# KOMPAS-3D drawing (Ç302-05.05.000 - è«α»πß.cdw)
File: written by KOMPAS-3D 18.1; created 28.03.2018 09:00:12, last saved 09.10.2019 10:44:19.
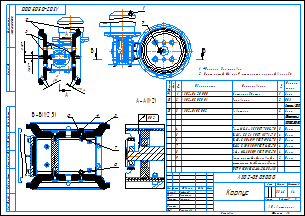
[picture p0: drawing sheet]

Sheet 1: A3, landscape

Document properties: Автор: Милов; Полное имя файла: ..\3Д ПВХ\А302-01.05.000 - Корпус.a3d; Масса: 33.4594

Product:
- Part/product: (unnamed)
  - Component: Болт М8-6gx35 ГОСТ 7805-70  | pos. 4  | Раздел спецификации: Стандартные изделия; Примечание: Нерж.
  - Component: Ловитель  | designation А302-01.05.002  | pos. 3  | Раздел спецификации: Детали; Форматы листов документа: А3; Примечание: Заим. / Фторопласт-4  / ГОСТ 10007-80 Е @2~50
  - Component: Основание  | designation А302-05.05.001  | pos. 2  | Раздел спецификации: Детали; Форматы листов документа: А3; Примечание: ПВХ / Стержень @2~300
  - Component: Мотор-редуктор  | designation А302-04.20.000  | pos. 1  | Раздел спецификации: Сборочные единицы; Форматы листов документа: *); Примечание: Заим.
  - Component: Шайба C.8.21 ГОСТ 11371-78  | pos. 5  | Раздел спецификации: Стандартные изделия; Примечание: Нерж.
  - Component: Шайба C 8.04.019 ГОСТ 6958-78  | pos. 6  | Раздел спецификации: Стандартные изделия; Примечание: Нерж.
  - Component: Шайба 8 30Х13 019 ГОСТ 6402-70  | pos. 7  | Раздел спецификации: Стандартные изделия; Примечание: Нерж.
  - Component: Гайка М8-6H.5.019 ГОСТ 5915-70  | pos. 8  | Раздел спецификации: Стандартные изделия; Примечание: Нерж
  - Component: Винт с потайной головкой и  / шестигранным углублением под ключ / ГОСТ Р ИСО 10642-М4x20-8.8-A3J  | pos. 9  | Раздел спецификации: Стандартные изделия; Примечание: Нерж.

Title block, sheet 1: Наименование: Корпус; designation: А302-05.05.000; Масса: 33,46; scale: 1:4; Количество листов документа: 1; organisation: АО «Астерион»; Форматы листов документа: A3; stored path: Z:\Мембранные насосы\Мембранный электропривод\А302-00.00.000 - ASTRA-302 (МЭ200)\Чертежи\А302-00.05.000 - Корпус.cdw; Разработал: Лифлянд; Проверил: Борисенко; Т. контр.: Лучихин; Утвердил: Григорьева

Views: Разрез В-В, Разрез А-А, Разрез Б-Б
Referenced files in \\192.168.87.28\Konstructor_doc\Мембранные насосы\Мембранный электропривод\А302-00.00.000 - ASTRA-302 (МЭ200)\3Д ПВХ\Отработка\: А302-01.05.000 - Корпус.a3d, А302-01.20.000 - Мотор-редуктор.a3d, А302-01.05.002 - Ловитель.m3d, Упор-1.m3d, Фиксатор.m3d
Referenced files in C:\Program Files\ASCON\KOMPAS-3D v18\Libs\PartLib\DATA\VAULT\methods\kompas\3d\: PLib_Check_spring_rings_GOST_13942_911.m3d, PLib_Washer_1_712.m3d, PLib_Bolt_1_900.m3d, PLib_Washer_2_712.m3d, PLib_Nut_OST92_900.m3d, PLib_Screw_DIN_7984_1500.m3d, PLib_Key_prismatic_712.m3d, PLib_Screw_ISO_10642_1500.m3d
Referenced files in D:\Мембранные насосы\Мембранный электропривод\А302-00.00.000 - ASTRA-302 (МЭ200)\3Д ПВХ\: А302-01.20.002 - Эксцентрик.m3d, FB 063 .m3d, А302-04.35.004 - Стенка.m3d, А302-04.35.003 - Опора подшиника.m3d, А302-01.20.001 - Основание.m3d, А302-01.35.000 - Фланец.a3d, А302-01.05.000 - Корпус.a3d, А302-01.05.011 - Ловитель.m3d, А302-01.05.015 - Фиксатор.m3d
Referenced files in D:\Мембранные насосы\Мембранный электропривод\А302-00.00.000 - ASTRA-302 (МЭ200)\3Д\: А302-00.35.002 - Пластина.m3d, А302-00.35.001 - Труба 140х140х4.m3d, А302-00.20.004 - Вал.m3d, А302-00.20.003 - Ползун.m3d, А302-00.05.001 - Основание.m3d
Referenced files in D:\1 ПКИ 3D\1 Крепеж стандартный\Подшипник\: Подшипник 52х25х15 62052RSH SKF.m3d, Подшипник 80х40х18 6208-2RS1 SKF.m3d
Referenced files in D:\1 ПКИ 3D\Редуктора NMRW\Редукторы\: Редуктор NMRW 063.m3d, Червячный мотор-редуктор NMRV063 АИР80.a3d
Referenced files in Z:\Мембранные насосы\Мембранный электропривод\А302-00.00.000 - ASTRA-302 (МЭ200)\3Д ПВХ\: А302-01.20.000 - Мотор-редуктор.cdw
Referenced files in \\192.168.87.28\Konstructor_doc\Мембранные насосы\Мембранный электропривод\А302-00.00.000 - ASTRA-302 (МЭ200)\3Д ПВХ\: А302-01.05.002 - Ловитель.cdw, А302-01.05.001 - Основание.m3d, А302-01.05.001 - Основание.cdw, А302-01.05.012 - Фиксатор.m3d, А302-01.05.012 - Фиксатор.cdw, А302-01.05.014 - Упор.cdw, А302-01.05.011 - Ловитель.m3d, А302-01.05.011 - Ловитель.cdw, А302-01.05.015 - Фиксатор.m3d, А302-01.05.015 - Фиксатор.cdw, А302-01.20.002 - Эксцентрик.m3d
Referenced files in \\192.168.87.28\Konstructor_doc\1 ПКИ 3D\1 Крепеж стандартный\Подшипник\: Подшипник 80х40х18 6208-2RS1 SKF.m3d, Подшипник 52х25х15 62052RSH SKF.m3d
Referenced files in D:\Мембранные насосы\Мембранный электропривод\А302-00.00.000 - ASTRA-302 (МЭ200)\3Д ПВХ\Отработка\: А302-01.20.000 - Мотор-редуктор.a3d, А302-01.05.002 - Ловитель.m3d, Фиксатор.m3d, Упор-1.m3d
Referenced files in D:\1 ПКИ 3D\Двигатели\АИР\: Электродвигатель АИР 80А4 IM 3081 1,1кВт 1400 об..m3d
Referenced files in C:\Program Files\ASCON\KOMPAS-3D V16\Libs\PartLib\DATA\VAULT\Methods\kompas\3d\: PLib_Bolt_1_900.m3d
Referenced files in Z:\Мембранные насосы\Мембранный электропривод\А302-00.00.000 - ASTRA-302 (МЭ200)\3Д\: А302-00.20.002 - Эксцентрик.m3d
Referenced files in C:\Program Files\ASCON\KOMPAS-3D V16\Libs\PartLib\DATA\vault\Methods\Kompas\3D\: PLib_Check_spring_rings_GOST_13942_911.m3d, PLib_Washer_2_712.m3d, PLib_Washer_1_712.m3d, PLib_Screw_DIN_7984_1500.m3d
Referenced files in \\192.168.87.28\Konstructor_doc\Мембранные насосы\Мембранный электропривод\А302-00.00.000 - ASTRA-302 (МЭ200)\3Д\: А302-00.20.004 - Вал.m3d, А302-00.35.001 - Труба 140х140х4.m3d, А302-00.35.002 - Пластина.m3d, А302-00.20.003 - Ползун.m3d
Referenced files in \\192.168.87.28\Konstructor_doc\1 ПКИ 3D\Двигатели\АИР\: Электродвигатель АИР 80А4 IM 3081 1,1кВт 1400 об..m3d
Referenced files in \\192.168.87.28\Konstructor_doc\1 ПКИ 3D\Редуктора NMRW\Редукторы\: Редуктор NMRW 063.m3d
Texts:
  Мотор-редуктор
  @100~)2xA3
  Ловитель
  Основание
  Шайба C.8.21 ГОСТ 11371-78
  Крепежное изделие ГОСТ
  Шайба
  ГОСТ
  нерж.
  Сталь 12Х18Н10Т ГОСТ 5632-72
  Шайба C 8 ГОСТ 6958-78
  Сталь 20 ГОСТ 1050-2013
  Шайба C 8.04.019 ГОСТ 6958-78
  Шайба 8 ГОСТ 6402-70
  Сталь 30Х13 ГОСТ 5632-72
  Шайба 8 30Х13 019 ГОСТ 6402-70
  Болт М8-6gx30 ГОСТ 7805-70
  Болт
  Болт М8-6gx30.58.019 ГОСТ 7805-70
  Гайка М8-6H ГОСТ 5915-70
  Гайка
  Гайка М8-6H.5.019 ГОСТ 5915-70
  Подшипник 80х40х18 6208-2RS1 SKF
  Подшипник
  SKF
  Фиксатор
  Упор
  Шайба C.5.21 ГОСТ 11371-78
  Шайба 5 ГОСТ 6402-70
  Винт с цилиндрической головкой
  и шестигранным углублением под ключ
  ГОСТ Р ИСО  4762-М5 x 16
  Винт с цилиндрической головкой и шестигранным углублением под ключ
  Р ИСО
  Сталь
  Шайба 5 30Х13 019 ГОСТ 6402-70
  Винт с цилиндрической головкой и шестигранным углублением под ключ ГОСТ Р ИСО  4762-М5 x 16-6.8-A9J
  ГОСТ Р ИСО  4762-М5 x 12
  Винт с цилиндрической головкой и шестигранным углублением под ключ ГОСТ Р ИСО  4762-М5 x 12-6.8-A9J
  Винт с потайной головкой
  ГОСТ Р ИСО  10642-М4 x 20
  Винт с потайной головкой и шестигранным углублением под ключ
  Винт с потайной головкой и шестигранным углублением под ключ ГОСТ Р ИСО  10642-М4 x 20-8.8-A3J
  ГОСТ Р ИСО  4762-М8 x 45
  Винт с цилиндрической головкой и шестигранным углублением под ключ ГОСТ Р ИСО  4762-М8 x 45-6.8-A9J
  ГОСТ Р ИСО  4762-М8 x 35
  Винт с цилиндрической головкой и шестигранным углублением под ключ ГОСТ Р ИСО  4762-М8 x 35-6.8-A9J
  Кольцо A40.65Г ГОСТ 13942-86
  Кольцо
  Сталь 65Г ГОСТ 14959-79
  Винт
  потайной
  головкой
  шестигранным
  углублением
  под
  ключ
  ИСО
  цилиндрической
  Заим.
  ПВХ
  Стержень  300
  ПВХ / Стержень @2~300
  Фторопласт-4
  ГОСТ 10007-80 Е  50
  Заим. / Фторопласт-4  / ГОСТ 10007-80 Е @2~50
  Болт М8-6gx35 ГОСТ 7805-70
  Нерж.
  Нерж
  Винт с потайной головкой и
  шестигранным углублением под ключ
  ГОСТ Р ИСО 10642-М4x20-8.8-A3J
  Электродвигатель / АИР 80А4 IM 3081 1,1кВт 1400 об/мин
  Редуктор NMRW 063
  Мотор-редуктор / NMRV063 N P(кВт) V5 / P(мощн./дв.), i(передат. отн.) см. заказ
  Пластина
  Труба 140х140х6
  Опора подшипника
  Стенка
  Фланец
  Эксцентрик
  Кольцо A25.65Г ГОСТ 13942-86
  Подшипник 52х25х15 62052RSH SKF
  Вал
  Ползун
  Шайба C.6.21 ГОСТ 11371-78
  Болт М6-6gx40 ГОСТ 7805-70
  Шайба 6 30Х13 019 ГОСТ 6402-70
  Гайка М6-6H.21.12Х18Н10Т ГОСТ 5915-70
  Винт с цилиндрической головкой и шестигранным углублением под ключ ГОСТ Р ИСО 4762 - М8 x 25 - A2-70
  Гайка М8-6H.21.12Х18Н10Т ГОСТ 5915-70
  Шпонка 8x7x90 ГОСТ 23360-78
  FB 063
  Винт с цилиндрической головкой и шестигранным углублением под ключ ГОСТ Р ИСО 4762-М8 x 25-A2-70
  Болт М8-6gx35.58.019 ГОСТ 7805-70
  Винт с потайной головкой и шестигранным углублением под ключГОСТ Р ИСО 10642-М4x20-8.8-A3J
Dimensions and other numbers on the sheet: 0,02; 4; 1; 3; 2; 20; 21; 40Х; 019; 18; 8; 04; 17; 58; 30Х13; 14; 5; 6; 19; 16; 11; 6.8; 10; 9; 8.8; 13; 12; 15; 65Г; 7; 34; 0; 46; 42; 54; 49; 44; 30; 31; 40; 51; 53; 41; 1:4; 33,46

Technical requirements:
  *Размеры для справок.
  Винт потай М4 поз.9 стопорить краской в резьбу.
